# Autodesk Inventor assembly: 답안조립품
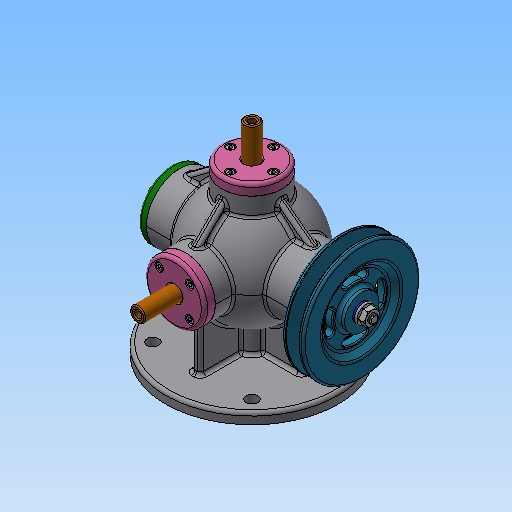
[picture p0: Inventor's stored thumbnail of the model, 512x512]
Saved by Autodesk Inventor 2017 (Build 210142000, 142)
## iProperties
Part Number: 답안조립품
Material: 일반
Document SubType Name: Assembly
Designer: MRC
Author: MRC
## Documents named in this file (17)
- C:\Users\MRC\Desktop\620909V1005\620909V1005\답안조립품.iam
- C:\Users\MRC\Desktop\620909V1005\620909V1005\본체.ipt
- C:\Users\MRC\Desktop\620909V1005\620909V1005\V-벨트풀리.ipt
- C:\Users\MRC\Desktop\620909V1005\620909V1005\너트-M8x1.ipt
- C:\Users\MRC\Desktop\620909V1005\620909V1005\뒤커버.ipt
- C:\Users\MRC\Desktop\620909V1005\620909V1005\베어링- 6202.ipt
- C:\Users\MRC\Desktop\620909V1005\620909V1005\본체커버.ipt
- C:\Users\MRC\Desktop\620909V1005\620909V1005\볼트 M4x0.7.ipt
- C:\Users\MRC\Desktop\620909V1005\620909V1005\슬라이드 커버.ipt
- C:\Users\MRC\Desktop\620909V1005\620909V1005\슬라이드.ipt
- C:\Users\MRC\Desktop\620909V1005\620909V1005\앞커버.ipt
- C:\Users\MRC\Desktop\620909V1005\620909V1005\오일실.ipt
- C:\Users\MRC\Desktop\620909V1005\620909V1005\와셔 8x17.ipt
- C:\Users\MRC\Desktop\620909V1005\620909V1005\축.ipt
- C:\Users\MRC\Desktop\620909V1005\620909V1005\키-4x4.ipt
- C:\Users\MRC\Desktop\620909V1005\620909V1005\가변스프링1.ipt
- C:\Users\MRC\Desktop\620909V1005\620909V1005\가변스프링2.ipt
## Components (20 placed, 4 different names)
1. V-벨트풀리:1
2. M4x0.7x12:5
3. 가변스프링1:1
4. 가변스프링2:1
5. M4x0.7x12:4
6. M4x0.7x12:6
7. M4x0.7x12:7
8. M4x0.7x12:8
9. M4x0.7x12:1
10. M4x0.7x12:9
11. M4x0.7x12:10
12. M4x0.7x12:11
13. M4x0.7x12:2
14. M4x0.7x12:12
15. M4x0.7x12:13
16. M4x0.7x12:14
17. M4x0.7x12:3
18. M4x0.7x12:15
19. M4x0.7x12:16
20. M4x0.7x12:17
